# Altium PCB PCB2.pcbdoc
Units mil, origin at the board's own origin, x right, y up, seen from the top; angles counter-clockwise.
Board outline 3539.97 x 3500 mil, 2 copper layers (Top Layer, Bottom Layer); 15 components, 30 nets, 98 pads, 17 vias.
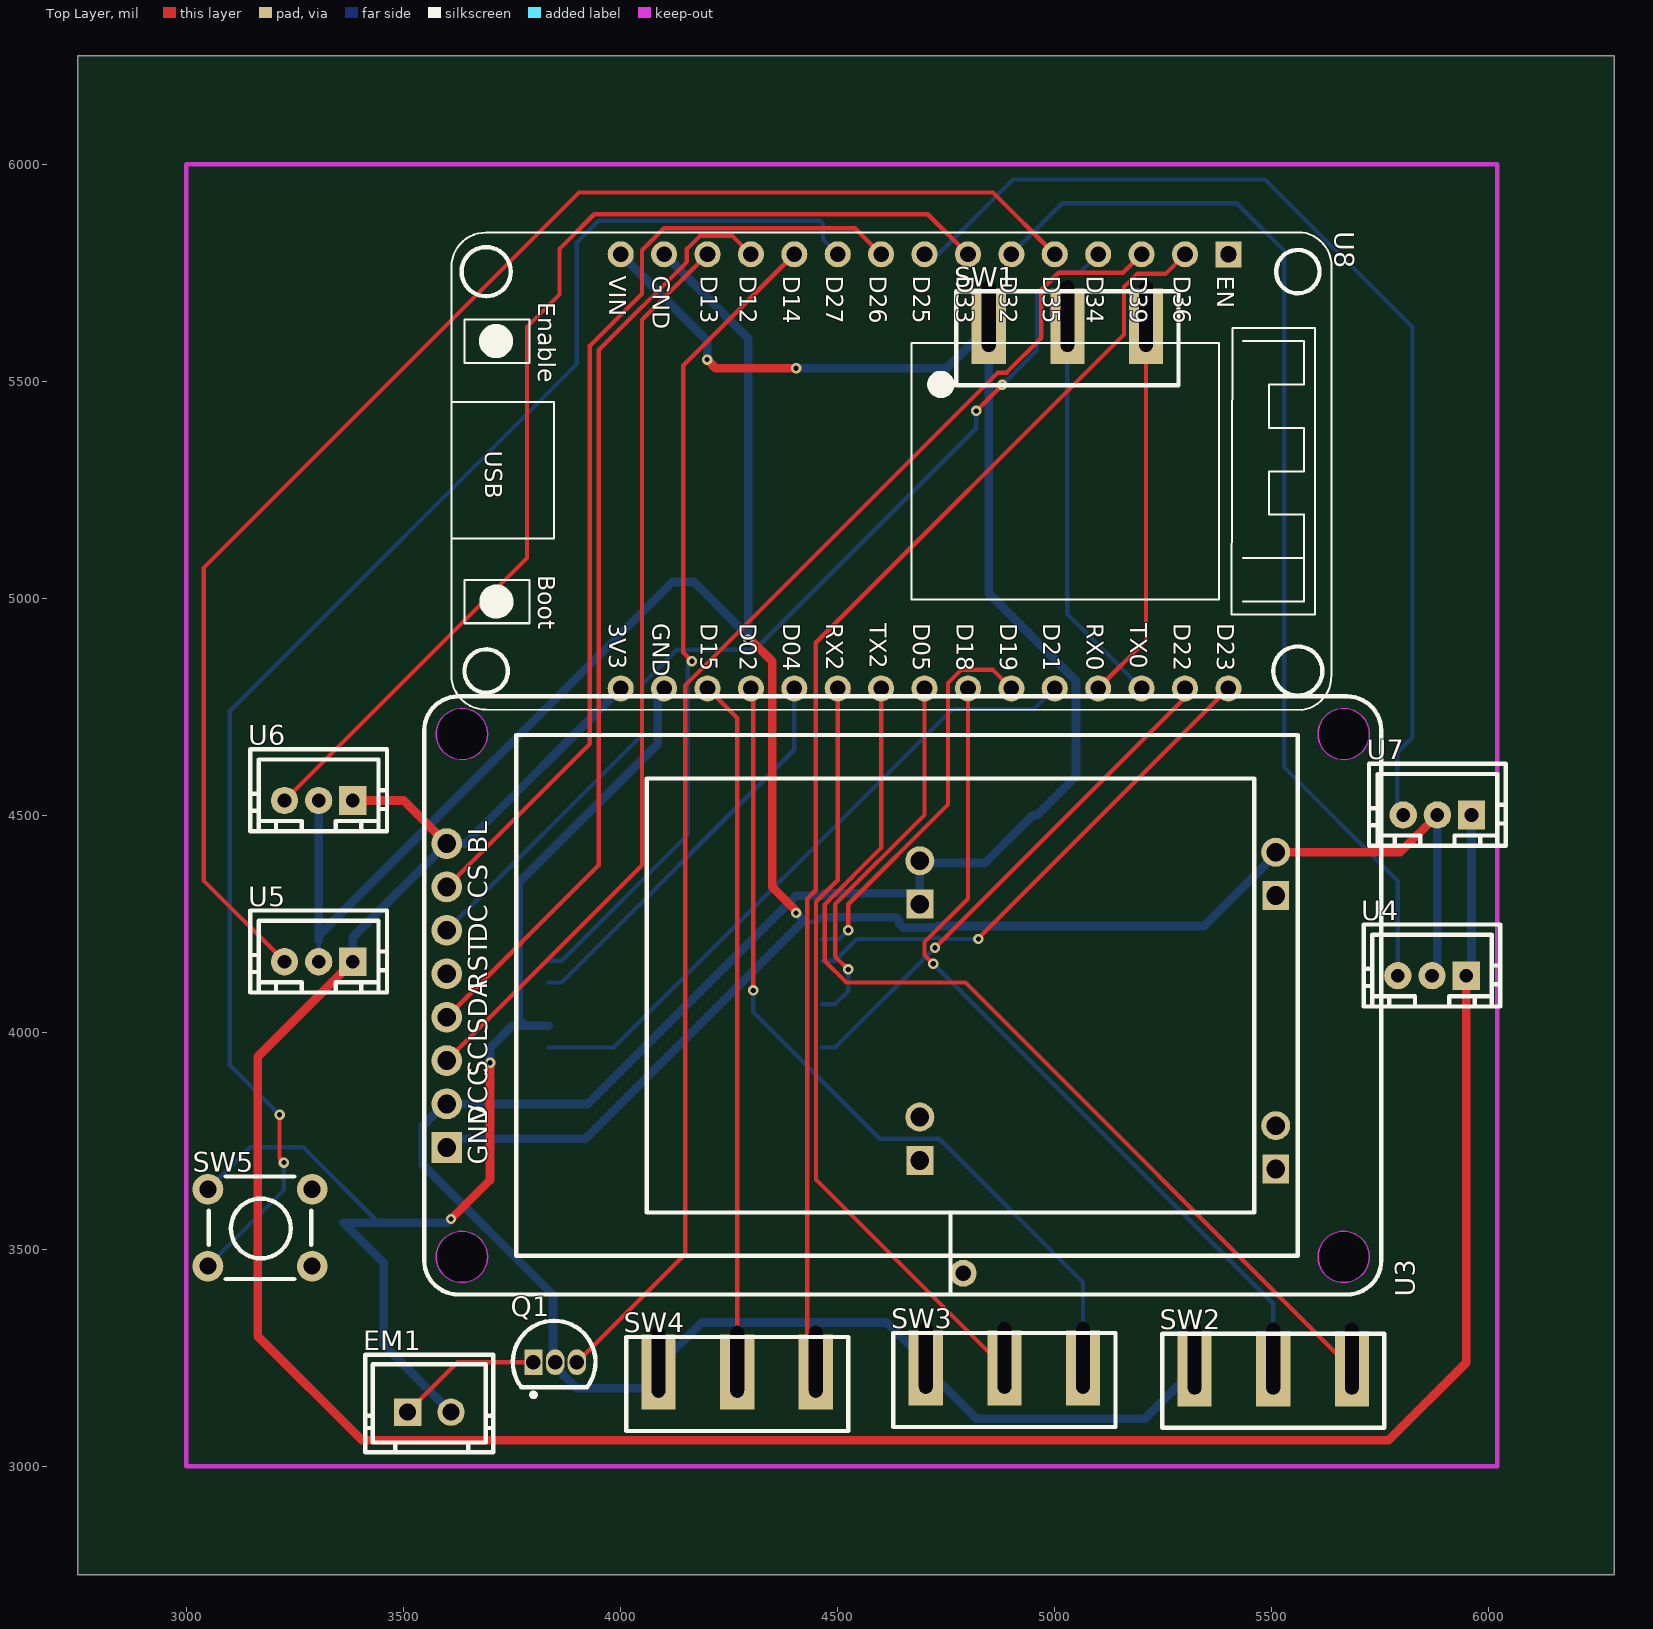
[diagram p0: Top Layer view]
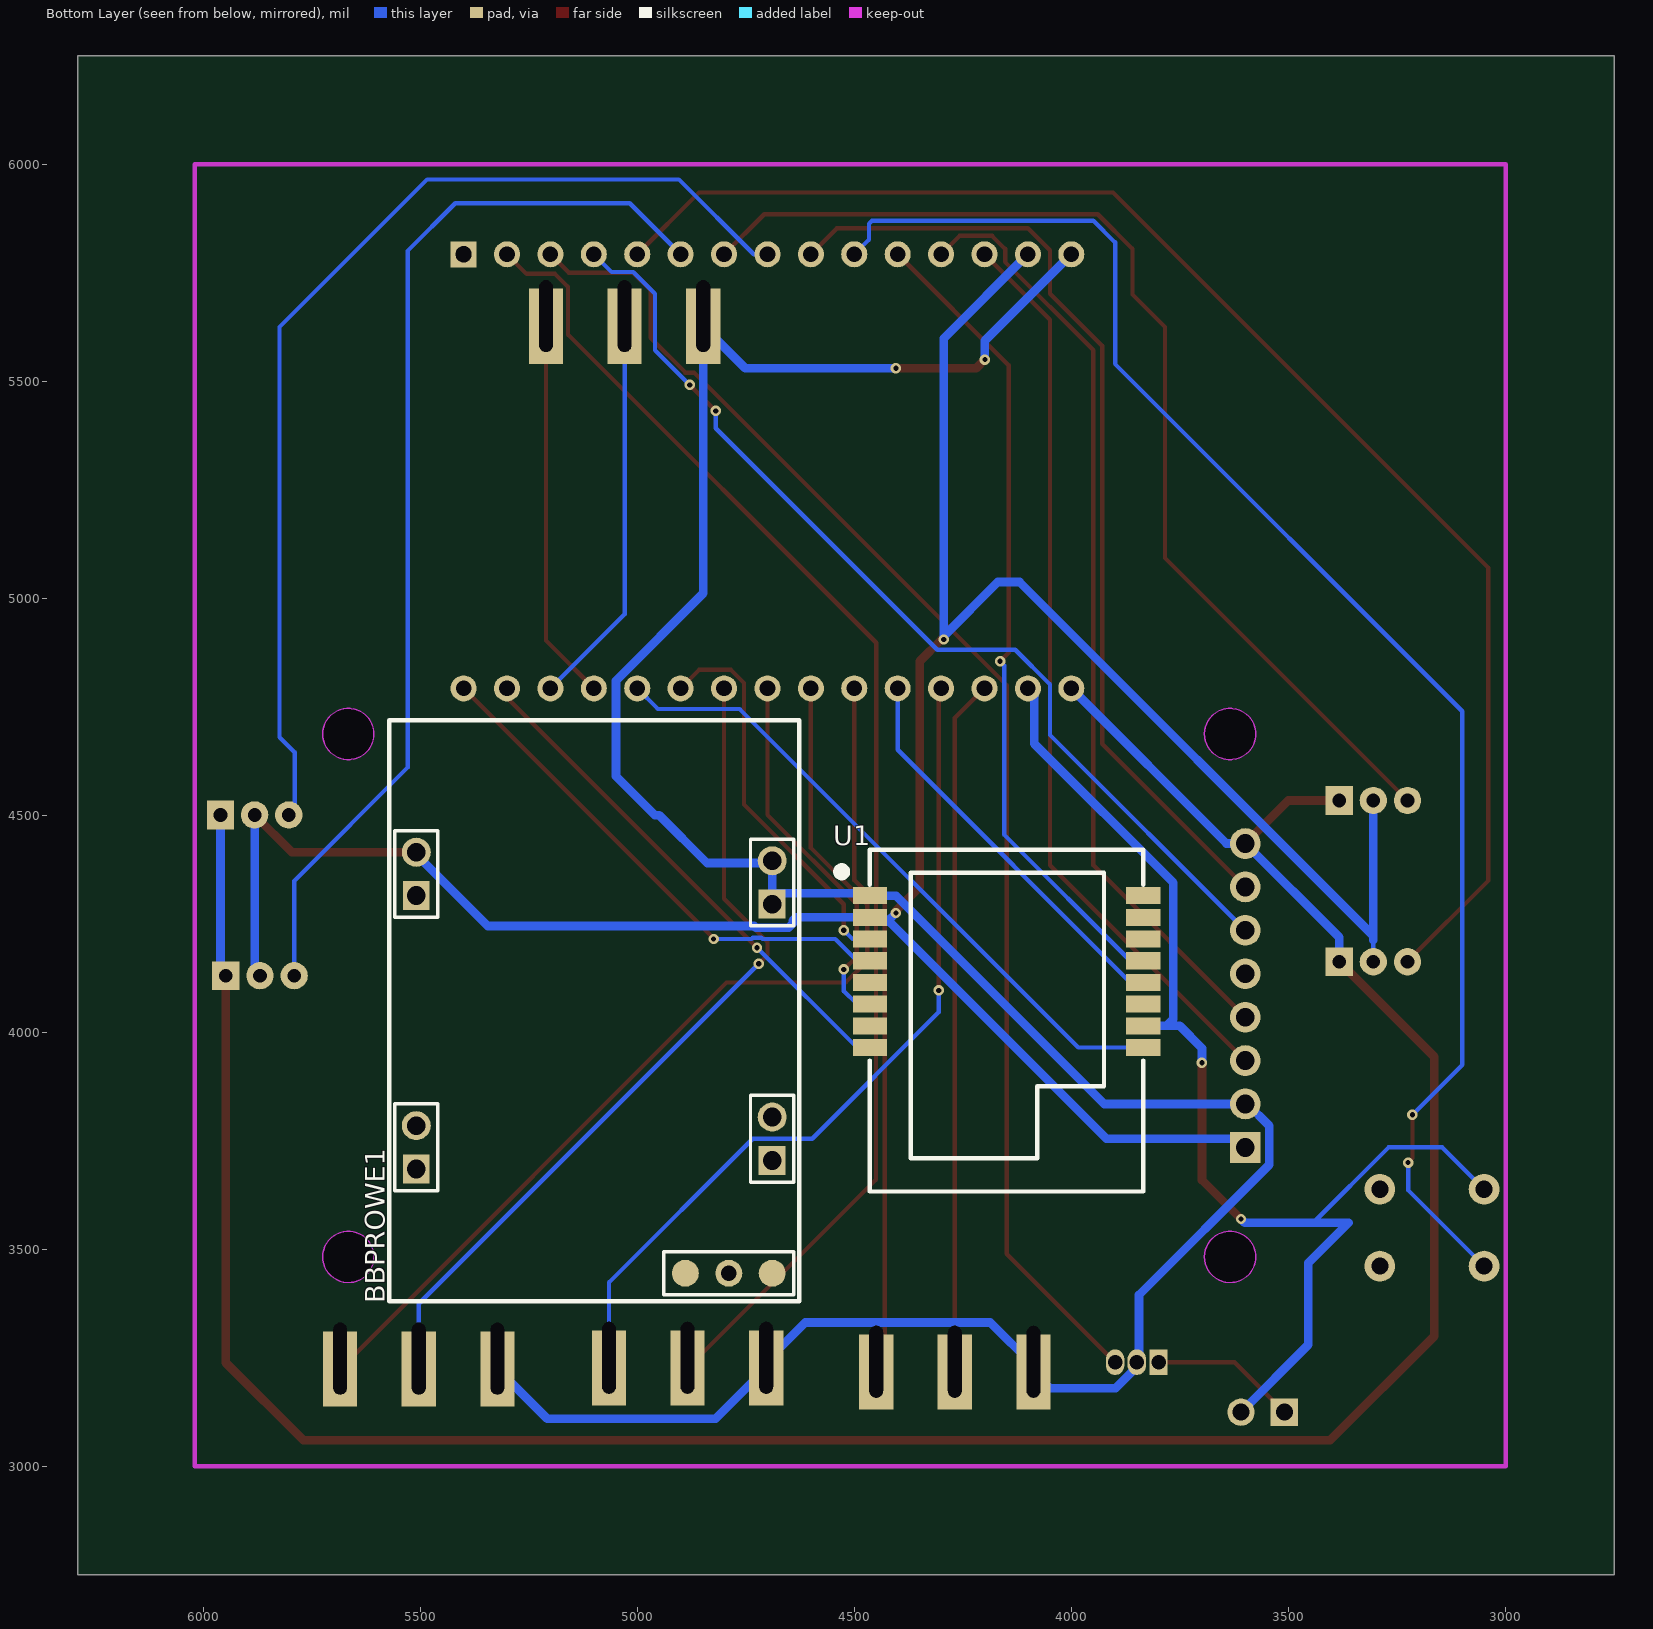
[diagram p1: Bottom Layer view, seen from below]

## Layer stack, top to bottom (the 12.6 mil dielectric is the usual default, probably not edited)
Top Layer: signal copper (thickness not stored)
Dielectric: dielectric 12.6, FR-4, Dk 4.8
Bottom Layer: signal copper (thickness not stored)

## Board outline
6289.97,2750 2750,2750 2750,6250 6289.97,6250

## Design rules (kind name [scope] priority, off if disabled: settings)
BoardOutlineClearance copperThickness1oz [All] p0: genericclearance=10 ignorepadtopadclearanceinfootprint=FALSE except(0: Arc-SplitContinuation Track-SplitContinuation SMDPad-SplitContinuation THPad-SplitContinuation Via-SplitContinuation Fill-SplitContinuation Poly-SplitContinuation Region-SplitContinuation Text-SplitContinuation; 6: Track-CutoutEdge SMDPad-CutoutEdge THPad-CutoutEdge Via-CutoutEdge Region-CutoutEdge; 11.8: Track-OutlineEdge SMDPad-OutlineEdge THPad-OutlineEdge Via-OutlineEdge Fill-OutlineEdge Region-OutlineEdge Poly-OutlineEdge Text-OutlineEdge Fill-CutoutEdge)
BoardOutlineClearance copperThickness2oz [All] p0: genericclearance=10 ignorepadtopadclearanceinfootprint=FALSE except(0: Arc-SplitContinuation Track-SplitContinuation SMDPad-SplitContinuation THPad-SplitContinuation Via-SplitContinuation Fill-SplitContinuation Poly-SplitContinuation Region-SplitContinuation Text-SplitContinuation; 6: Track-CutoutEdge SMDPad-CutoutEdge THPad-CutoutEdge Via-CutoutEdge Region-CutoutEdge; 11.8: Track-OutlineEdge SMDPad-OutlineEdge THPad-OutlineEdge Via-OutlineEdge Fill-OutlineEdge Region-OutlineEdge Poly-OutlineEdge Text-OutlineEdge Fill-CutoutEdge)
Clearance copperThickness1oz [(InNet('$1N1359') OR InNet('$1N2226') OR InNet('$1N1760') OR InNet('$1N1700') OR InNet('$1N1708') OR InNet('$1N1714') OR InNet('$1N1721') OR InNet('$1N1728') OR InNet('$1N1735') OR InNet('$1N1742') OR InNet('$1N1753') OR InNet('$1N1588') OR InNet('$1N2129') OR InNet('$1N1554') OR InNet('$1N1582') OR InNet('$1N1538') OR InNet('$1N1545') OR InNet('$1N1532') OR InNet('$1N1520') OR InNet('$1N1514') OR InNet('$1N1780') OR InNet('$1N1788') OR InNet('$1N1773') OR InNet('$1N1766') OR InNet('$1N1841') OR InNet('$1N2512') OR InNet('$1N2620') OR InNet('$1N2535') OR InNet('$1N2549') OR InNet('$1N2488'))] p1: gap=7 ignorepadtopadclearanceinfootprint=FALSE except(4: Track-Track; 6: Track-SMDPad SMDPad-SMDPad Track-THPad SMDPad-THPad THPad-THPad Track-Via SMDPad-Via THPad-Via Via-Via SMDPad-Fill THPad-Fill Via-Fill Fill-Fill Track-Region SMDPad-Region THPad-Region Via-Region Region-Region Track-Poly SMDPad-Poly THPad-Poly Via-Poly Fill-Poly Region-Poly Poly-Poly Track-Text SMDPad-Text THPad-Text Via-Text Fill-Text Region-Text Poly-Text Text-Text; 6.9: Track-Hole SMDPad-Hole THPad-Hole Via-Hole Fill-Hole Region-Hole Poly-Hole Text-Hole Sheet-Hole; 11.8: Track-Fill Fill-Region Track-Sheet SMDPad-Sheet THPad-Sheet Via-Sheet Fill-Sheet Region-Sheet Poly-Sheet Text-Sheet)
Clearance copperThickness2oz [All] p1: gap=7 ignorepadtopadclearanceinfootprint=FALSE except(6: Track-SMDPad SMDPad-SMDPad Track-THPad SMDPad-THPad THPad-THPad Track-Via SMDPad-Via THPad-Via Via-Via SMDPad-Fill THPad-Fill Via-Fill Fill-Fill Track-Region SMDPad-Region THPad-Region Via-Region Region-Region Track-Poly SMDPad-Poly THPad-Poly Via-Poly Fill-Poly Region-Poly Poly-Poly Track-Text SMDPad-Text THPad-Text Via-Text Fill-Text Region-Text Poly-Text Text-Text; 6.9: Track-Hole SMDPad-Hole THPad-Hole Via-Hole Fill-Hole Region-Hole Poly-Hole Text-Hole Sheet-Hole; 8: Track-Track; 11.8: Track-Fill Fill-Region Track-Sheet SMDPad-Sheet THPad-Sheet Via-Sheet Fill-Sheet Region-Sheet Poly-Sheet Text-Sheet)
DiffPairsRouting differentialPair [All] p1: maxuncoupledlength=10 minlimit=6 maxlimit=6 mostfreqgap=6 toplayer_minwidth=5 toplayer_prefwidth=10 toplayer_maxwidth=100 bottomlayer_minwidth=5 bottomlayer_prefwidth=10 bottomlayer_maxwidth=100
PasteMaskExpansion pasteMaskExpansion [All] p1: expansion=0
PlaneConnect innerPlane [All] p1: planeconnectstyle=Relief reliefexpansion=20 reliefentries=4 reliefconductorwidth=10 reliefairgap=10
PolygonConnect copperRegion [All] p1: connectstyle=Relief reliefentries=4 reliefconductorwidth=10 polygonreliefangle="90 Angle" airgapwidth=10
RoutingVias viaSize [All] p1: viastyle="Through Hole" holewidth=12.0078 minholewidth=11.811 maxholewidth=248.0314 width=24.0158 minwidth=19.685 maxwidth=393.7008
SolderMaskExpansion solderMaskExpansion [All] p1: useseparateexpansions=TRUE expansion=2 expansionbottom=2
Width copperThickness1oz [All] p1: maxlimit=100 minlimit=5 preferedwidth=10
Width copperThickness2oz [All] p1: maxlimit=100 minlimit=8 preferedwidth=10

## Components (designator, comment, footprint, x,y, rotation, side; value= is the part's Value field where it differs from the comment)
BBPROWE1 "TPS63020_Module" TPS63020_MODULE_PCB 5100,4050 r90 bottom
EM1 "GVI AC Fan" CONN-TH_2P-P2.54-V 3560,3125 r0 top
Q1 "3DD13003A" TO-92-3_L4.8-W3.7-P1.27-L 3850,3240 r0 top
SW1 "3_Position_Toggle_Switch" 3_Pin_Toggle_Switch_Footprint 5030,5540 r0 top
SW2 "3_Position_Toggle_Switch" 3_Pin_Toggle_Switch_Footprint 5504.29,3138.08 r0 top
SW3 "3_Position_Toggle_Switch" 3_Pin_Toggle_Switch_Footprint 4885,3140 r0 top
SW4 "3_Position_Toggle_Switch" 3_Pin_Toggle_Switch_Footprint 4269.29,3130.84 r0 top
SW5 "Button-6x6x6mm" SW-TH_4PIN-L6.00-W6.00 3170,3550 r0 top
U1 "E28-2G4M27SX" WIRELM-SMD_E28-2G4M27SX 4150,4140 r180 bottom
U3 "WeAct 1.8inch TFT Display ST7735" "WeAct 1.8 inch TFT ST7735S" 3600,3735 r90 top
U4 "JST-PH_3-PIN_2.0MM" "JST PH 3-PIN 2.0MM TOP ENTRY" 5712.62,4059.64 r0 top
U5 "JST-PH_3-PIN_2.0MM" "JST PH 3-PIN 2.0MM TOP ENTRY" 3147.62,4091.73 r0 top
U6 "JST-PH_3-PIN_2.0MM" "JST PH 3-PIN 2.0MM TOP ENTRY" 3147.62,4463.31 r0 top
U7 "JST-PH_3-PIN_2.0MM" "JST PH 3-PIN 2.0MM TOP ENTRY" 5725,4430 r0 top
U8 "ESP32 DEVKIT 30PIN" "ESP32 DEVKIT 30P" 5560,5765 r270 top

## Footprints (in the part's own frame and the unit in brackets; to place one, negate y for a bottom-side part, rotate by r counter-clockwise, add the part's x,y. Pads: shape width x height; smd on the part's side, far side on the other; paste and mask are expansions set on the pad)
3_Pin_Toggle_Switch_Footprint [mm]
  rect 2x4.4 hole 0.8 slot 4.2 at 90 deg copper offset 0,-0.6: 1(-4.6,2.8) 2(0,2.8) 3(4.6,2.8)
  silkscreen extent -6.5,-1.25 6.5,4.25
CONN-TH_2P-P2.54-V [mm]
  rect 1.6x1.6 hole 1: L(-1.27,0)
  round 1.6 hole 1: N(1.27,0)
  silkscreen extent -3.75,-2.34 3.75,3.36
"ESP32 DEVKIT 30P" [mil]
  rect 60x60 hole 36 slot 37.8 at 0 deg copper offset 0.01,-0.01: 1(-27.56,-159.05)
  round 60 hole 36 copper offset 0.01,-0.02: 2(-27.56,-259.05) 3(-27.56,-359.05) 4(-27.56,-459.05) 5(-27.56,-559.05) 6(-27.56,-659.05) 7(-27.56,-759.05) 8(-27.56,-859.05) 9(-27.56,-959.05) 10(-27.56,-1059.05) 11(-27.56,-1159.05) 12(-27.56,-1259.05) 13(-27.56,-1359.05) 14(-27.56,-1459.05) 16(972.44,-159.05) 17(972.44,-259.05) 18(972.44,-359.05) 19(972.44,-459.05) 20(972.44,-559.05) 21(972.44,-659.05) 22(972.44,-759.05) 23(972.44,-859.05) 24(972.44,-959.05) 25(972.44,-1059.05) 26(972.44,-1159.05) 27(972.44,-1259.05) 28(972.44,-1359.05) 29(972.44,-1459.05)
  round 60 hole 36 copper offset 0.01,-0.01: 15(-27.56,-1559.05) 30(972.44,-1559.05)
  silkscreen extent -78,-1949 1022,79
"JST PH 3-PIN 2.0MM TOP ENTRY" [mm]
  rect 1.6x1.676 hole 0.8: 1(6,1.8)
  round 1.6 hole 0.8: 2(4,1.801) 3(1.999,1.801)
  silkscreen extent 0,0 8,4.8
SW-TH_4PIN-L6.00-W6.00 [mm]
  round 1.8 hole 1: 1(-3.05,2.25) 2(3.05,2.25) 3(-3.05,-2.25) 4(3.05,-2.25)
  silkscreen extent -3,-3 3,3
TO-92-3_L4.8-W3.7-P1.27-L [mm]
  rect 1.07x1.5 hole 0.85: 1(-1.27,0)
  oval 1.07x1.5 hole 0.85: 2(0,0) 3(1.27,0)
  silkscreen extent -2.48,-2.03 2.36,2.43
TPS63020_MODULE_PCB [mil]
  rect 66.93x62 hole 43.31: 1(-364.96,410) 3(264.96,410) 5(-345.28,-410) 7(245.28,-410)
  round 66.93 hole 43.31: 2(-264.96,410) 4(364.96,410) 6(-245.28,-410) 8(345.28,-410)
  round 62 smd: 9(-605,-410) 11(-605,-210)
  round 62 hole 35: 10(-605,-310)
  silkscreen extent -669,-472 669,472
"WeAct 1.8 inch TFT ST7735S" [mm]
  rect 1.8x1.8 hole 1.1: 1(0,0)
  round 1.8 hole 1.1: 2(2.54,0) 3(5.08,0) 4(7.62,0) 5(10.16,0) 6(12.7,0) 7(15.24,0) 8(17.78,0)
  Board Outline Layer circle w0.025: c-6.41,-0.889 r1.5
  Board Outline Layer circle w0.025: c24.19,-0.889 r1.5
  Board Outline Layer circle w0.025: c-6.41,-52.489 r1.5
  Board Outline Layer circle w0.025: c24.19,-52.489 r1.5
  Board Outline Layer region: -6.41,-2.389 -7.061,-2.24 -7.583,-1.824 -7.872,-1.223 -7.872,-0.555 -7.583,0.046 -7.061,0.462 -6.41,0.611 -6.41,0.611 -5.759,0.462 -5.237,0.046 -4.948,-0.555 -4.948,-1.223 -5.237,-1.824 -5.759,-2.24 -6.41,-2.389
  Board Outline Layer region: 24.19,-2.389 23.539,-2.24 23.017,-1.824 22.728,-1.223 22.728,-0.555 23.017,0.046 23.539,0.462 24.19,0.611 24.19,0.611 24.841,0.462 25.363,0.046 25.652,-0.555 25.652,-1.223 25.363,-1.824 24.841,-2.24 24.19,-2.389
  Board Outline Layer region: -6.41,-53.989 -7.061,-53.84 -7.583,-53.424 -7.872,-52.823 -7.872,-52.155 -7.583,-51.554 -7.061,-51.138 -6.41,-50.989 -6.41,-50.989 -5.759,-51.138 -5.237,-51.554 -4.948,-52.155 -4.948,-52.823 -5.237,-53.424 -5.759,-53.84 -6.41,-53.989
  Board Outline Layer region: 24.19,-53.989 23.539,-53.84 23.017,-53.424 22.728,-52.823 22.728,-52.155 23.017,-51.554 23.539,-51.138 24.19,-50.989 24.19,-50.989 24.841,-51.138 25.363,-51.554 25.652,-52.155 25.652,-52.823 25.363,-53.424 24.841,-53.84 24.19,-53.989
  Multi-Layer board cut-out: -6.41,-2.389 -7.061,-2.24 -7.583,-1.824 -7.872,-1.223 -7.872,-0.555 -7.583,0.046 -7.061,0.462 -6.41,0.611 -6.41,0.611 -5.759,0.462 -5.237,0.046 -4.948,-0.555 -4.948,-1.223 -5.237,-1.824 -5.759,-2.24 -6.41,-2.389
  Multi-Layer board cut-out: 24.19,-2.389 23.539,-2.24 23.017,-1.824 22.728,-1.223 22.728,-0.555 23.017,0.046 23.539,0.462 24.19,0.611 24.19,0.611 24.841,0.462 25.363,0.046 25.652,-0.555 25.652,-1.223 25.363,-1.824 24.841,-2.24 24.19,-2.389
  Multi-Layer board cut-out: -6.41,-53.989 -7.061,-53.84 -7.583,-53.424 -7.872,-52.823 -7.872,-52.155 -7.583,-51.554 -7.061,-51.138 -6.41,-50.989 -6.41,-50.989 -5.759,-51.138 -5.237,-51.554 -4.948,-52.155 -4.948,-52.823 -5.237,-53.424 -5.759,-53.84 -6.41,-53.989
  Multi-Layer board cut-out: 24.19,-53.989 23.539,-53.84 23.017,-53.424 22.728,-52.823 22.728,-52.155 23.017,-51.554 23.539,-51.138 24.19,-50.989 24.19,-50.989 24.841,-51.138 25.363,-51.554 25.652,-52.155 25.652,-52.823 25.363,-53.424 24.841,-53.84 24.19,-53.989
  silkscreen extent -8.61,-54.69 26.39,1.31
WIRELM-SMD_E28-2G4M27SX [mm]
  rect 2x1 smd: 1(-8,4.445) 2(-8,3.175) 3(-8,1.905) 4(-8,0.635) 5(-8,-0.635) 6(-8,-1.905) 7(-8,-3.175) 8(-8,-4.445) 9(8,-4.445) 10(8,-3.175) 11(8,-1.905) 12(8,-0.635) 13(8,0.635) 14(8,1.905) 15(8,3.175) 16(8,4.445)
  silkscreen extent -9.9,-12.86 8,7.14

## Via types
v1: diameter 24.02, hole 12.01, Top Layer to Bottom Layer, 17 vias

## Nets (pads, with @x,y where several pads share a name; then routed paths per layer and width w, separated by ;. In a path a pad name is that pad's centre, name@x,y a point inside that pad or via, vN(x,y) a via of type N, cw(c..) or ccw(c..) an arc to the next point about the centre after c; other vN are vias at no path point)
$1N1359: BBPROWE1.4 U1.2 U3.1 U4.2 U5.2 U6.2 U7.2 U8.14 | length 6422.6
  Top Layer w20: v1(4294.96,4905) 4299.96,4905 4349.96,4855 4349.96,4335 4404.96,4280 v1(4404.96,4275) ; BBPROWE1.4 5796.56,4414.96 U7.2
  Bottom Layer w10: U5.2 3305.12,4212.63 ; 4424.96,4255 4454.96,4255 U1.2
  Bottom Layer w20: 3305.12,4212.63 U6.2 ; 3305.12,4222.63 4120.12,5037.63 4170.12,5037.63 v1@4294.96,4912.79 ; U3.1 3620,3755 3919.96,3755 4419.96,4255 4424.96,4255 v1(4404.96,4275) ; U8.14@4100.94,5792.55 4294.96,5598.52 v1@4294.96,4912.79 ; v1(4294.96,4905) v1@4294.96,4912.79 ; U1.2 4635.04,4265 4643.02,4257.02 4643.02,4250.19 4652.38,4240.83 4727.62,4240.83 4731.79,4245 5345.04,4245 BBPROWE1.4@5510,4409.96 ; U4.2 5882.5,4142.92 U7.2
$1N1514: U1.3 U8.21 | length 909.5
  Top Layer w10: v1(4524.96,4235) 4524.96,4295 4754.96,4525 4754.96,4805 4784.96,4835 4858.48,4835 U8.21@4900.94,4792.55
  Bottom Layer w10: U1.3 4504.96,4215 v1(4524.96,4235)
$1N1520: U1.4 U8.16 | length 1199.3
  Top Layer w10: v1(4824.96,4215) 4824.96,4216.57 U8.16@5400.94,4792.55
  Bottom Layer w10: U1.4 4494.96,4165 4544.96,4215 4712.44,4215 4715.44,4217.99 4734.48,4217.99 4737.48,4215 v1(4824.96,4215)
$1N1532: U1.6 U8.23 | length 867.7
  Top Layer w10: v1(4524.96,4145) 4494.96,4175 4494.96,4295 4700.94,4500.98 U8.23@4700.94,4792.55
  Bottom Layer w10: U1.6 4494.96,4065 4524.96,4095 v1(4524.96,4145)
$1N1538: U1.9 U8.20 | length 1508.7
  Bottom Layer w10: U1.9 3985.04,3965 4765.04,4745 4953.39,4745 U8.20@5000.94,4792.55
$1N1545: U1.8 U8.17 | length 1191.4
  Top Layer w10: v1(4724.96,4195) 5300.94,4770.98 U8.17@5300.94,4792.55
  Bottom Layer w10: U1.8 4494.96,3965 v1(4724.96,4195)
$1N1554: U1.13 U8.11 | length 1896.1
  Top Layer w10: v1(4165.04,4855) 4145.04,4875 4145.04,5536.65 U8.11@4400.94,5792.55
  Bottom Layer w10: U1.13 3865.04,4165 4155.04,4455 4155.04,4845 v1(4165.04,4855)
$1N1582: U1.12 U8.26 | length 929.5
  Bottom Layer w10: U1.12 3865.04,4115 4400.94,4650.9 U8.26@4400.94,4792.55
$1N1588: EM1.N SW5.1 U1.10 U8.29 | length 2805.6
  Top Layer w20: v1(3610,3570) 3700,3660 v1(3700,3930)
  Bottom Layer w10: SW5.1 3146.34,3735 3270,3735 3443.71,3561.29
  Bottom Layer w20: EM1.N 3454.92,3280.08 3454.92,3468.58 3362.21,3561.29 3443.71,3561.29 3601.29,3561.29 v1(3610,3570) ; v1(3700,3930) 3700,3963.66 3751.34,4015 3781.34,4015 ; U1.10 3781.34,4015 ; U8.29@4100.94,4792.55 4086.34,4777.95 4086.34,4665 3766.34,4345 3766.34,4030 3781.34,4015
$1N1700: SW1.2 U8.18 | length 904.9
  Bottom Layer w10: SW1.2@5030,5626.61 5030,4963.48 U8.18@5200.94,4792.55
$1N1708: SW1.3 U8.19 | length 879.7
  Top Layer w10: U8.19@5100.94,4792.55 5211.1,4902.72 SW1.3@5211.1,5626.61
$1N1714: SW2.2 U8.22 | length 1942
  Top Layer w10: v1(4720.94,4158.04) 4700.94,4178.04 4700.94,4208.04 4800.94,4308.04 U8.22@4800.94,4792.55
  Bottom Layer w10: v1(4720.94,4158.04) 5504.29,3374.69 SW2.2@5504.29,3224.69
$1N1721: SW2.3 U8.24 | length 2285.5
  Top Layer w10: U8.24@4600.94,4792.55 4600.94,4424.69 4470.94,4294.69 4470.94,4164.69 4520.94,4114.69 4795.39,4114.69 SW2.3@5685.39,3224.69
$1N1728: SW3.2 U8.25 | length 1766.4
  Top Layer w10: U8.25@4500.94,4792.55 4500.94,4350.68 4450.94,4300.68 4450.94,3660.68 SW3.2@4885,3226.61
$1N1735: SW3.3 U8.27 | length 1963.3
  Top Layer w10: U8.27@4300.94,4792.55 4306.1,4787.38 v1(4306.1,4096.61)
  Bottom Layer w10: v1(4306.1,4096.61) 4306.1,4046.61 4597.72,3755 4735,3755 5066.1,3423.9 SW3.3@5066.1,3226.61
$1N1742: SW4.2 U8.28 | length 1603.4
  Top Layer w10: U8.28@4200.94,4792.55 4269.29,4724.19 SW4.2@4269.29,3217.45
$1N1753: SW4.3 U8.2 | length 2982.3
  Top Layer w10: SW4.3@4450.39,3217.45 4430.39,3237.45 4430.39,4307.45 4450.39,4327.45 4450.39,4897.45 5160.39,5607.45 5160.39,5717.45 5190.39,5747.45 5255.84,5747.45 U8.2@5300.94,5792.55
$1N1760: Q1.3 U8.3 | length 3190.1
  Top Layer w10: Q1.3 4150,3490 4150,4800 4870,5520 4890,5520 4970,5600 4970,5710 5010,5750 5158.39,5750 U8.3@5200.94,5792.55
$1N1766: U3.3 U8.13 | length 2106.5
  Top Layer w10: U3.3 4050,4385 4050,5641.61 U8.13@4200.94,5792.55
$1N1773: U3.4 U8.12 | length 2176.8
  Top Layer w10: U3.4 3950,4385 3950,5571.61 4153.39,5775 4153.39,5805 4183.39,5835 4258.48,5835 U8.12@4300.94,5792.55
$1N1780: U3.7 U8.9 | length 2249.9
  Top Layer w10: U3.7 3930,4665 3930,5581.61 4050,5701.61 4050,5801.61 4100.94,5852.55 4540.94,5852.55 U8.9@4600.94,5792.55
$1N1788: U3.6 U8.4 | length 2314
  Top Layer w10: v1(4820,5431.61) v1(4880,5491.61)
  Bottom Layer w10: U3.6 4050,4685 4050,4801.61 4130,4881.61 4310,4881.61 4820,5391.61 v1(4820,5431.61) ; v1(4880,5491.61) 4960,5571.61 4960,5701.61 5010,5751.61 5060,5751.61 U8.4@5100.94,5792.55
$1N1841: U6.3 U8.7 | length 2545.6
  Top Layer w10: U6.3 3785,5092.89 3785,5625 3860,5700 3860,5805 3940,5885 4708.48,5885 U8.7@4800.94,5792.55
$1N2129: SW5.3 U8.10 | length 3489.4
  Top Layer w10: v1(3215,3810) 3215,3710 v1(3225,3700)
  Bottom Layer w10: SW5.3 3225,3636.5 v1(3225,3700) ; v1(3215,3810) 3100,3925 3100,4740 3900,5540 3900,5820 3950,5870 4460,5870 4467.07,5862.93 4467.07,5826.41 U8.10@4500.94,5792.55
$1N2226: EM1.L Q1.1 | length 337.6
  Top Layer w10: EM1.L 3625,3240 Q1.1
$1N2488: U7.3 U8.8 | length 2480.6
  Bottom Layer w10: U8.8@4700.94,5792.55 4732.55,5792.55 4905,5965 5485,5965 5825,5625 5825,4680 5790,4645 5790,4514.6 U7.3
$1N2512: BBPROWE1.7 BBPROWE1.8 Q1.2 SW1.1 SW2.1 SW3.1 SW4.1 U1.1 U3.2 U8.15 | length 6446.8
  Top Layer w20: v1(4200,5550) 4220,5530 v1(4405,5530)
  Bottom Layer w10: BBPROWE1.7@4690,4290.28 BBPROWE1.7@4690,4320.28
  Bottom Layer w20: U8.15@4000.93,5792.55 4200,5593.48 v1(4200,5550) ; v1(4405,5530) 4752.28,5530 4848.9,5626.61 4848.9,5011.38 5050,4810.28 5050,4590.28 4960,4500.28 4950,4500.28 4840,4390.28 4690,4390.28 4690,4320.28 4470.24,4320.28 U1.1 4404.96,4315 3924.96,3835 U3.2 3595,3835 3545,3785 3545,3695 3845,3395 3845,3245 Q1.2 3850,3230 3862.95,3217.05 3862.95,3216.19 3899.14,3180 4050.74,3180 4088.19,3217.45 4088.19,3232.45 4187.35,3331.61 4613.9,3331.61 4703.9,3241.61 4703.9,3226.61 4820.51,3110 5208.5,3110 SW2.1@5323.19,3224.69
$1N2535: U4.3 U8.6 | length 2501
  Bottom Layer w10: U8.6@4900.94,5792.55 5018.39,5910 5420,5910 5530,5800 5530,4610 5791.32,4348.68 U4.3
$1N2549: U5.3 U8.5 | length 3362.8
  Top Layer w10: U5.3 3226.32,4163.68 3040,4350 3040,5070 3905,5935 4858.48,5935 U8.5@5000.94,5792.55
$1N2620: U3.8 U4.1 U5.1 U6.1 U7.1 U8.30 | length 6345.9
  Top Layer w20: U5.1 3165,3943.76 3165,3300 3405,3060 5770,3060 5948.84,3238.84 U4.1 ; U6.1 3500.82,4534.18 U3.8
  Bottom Layer w20: U5.1 3383.84,4218.84 U3.8 3643.39,4435 U8.30@4000.93,4792.55 ; U4.1 5961.22,4142.89 U7.1
pads on no net: BBPROWE1.1 BBPROWE1.2 BBPROWE1.3 BBPROWE1.5 BBPROWE1.6 BBPROWE1.9 BBPROWE1.10 BBPROWE1.11 SW5.2 SW5.4 U1.5 U1.7 U1.11 U1.14 U1.15 U1.16 U3.5 U8.1

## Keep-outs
Board Outline Layer:
  lines w10: 3000,3000 6020,3000 6020,6000 3000,6000 3000,3000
